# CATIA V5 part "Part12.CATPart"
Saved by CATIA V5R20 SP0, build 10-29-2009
Part number: 9AE031620-4
Revision: ANY
Definition: UNKNOWN
Nomenclature: 9AE031620-4
Source: Unknown
Bounding box of the stored display mesh (mm): x -3.679 to 3.679, y -3.679 to 3.679, z 0 to 12.6
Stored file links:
  C:\Users\Utente\Desktop\IO LAVORO\3D X SITO CF\CUMSA\3D files AE\AE 041620\Part12.CATPart
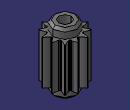
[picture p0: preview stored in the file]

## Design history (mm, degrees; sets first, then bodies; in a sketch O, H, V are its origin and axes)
Body1 "Chaflán1" (main body)
  Solid1: solid without history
